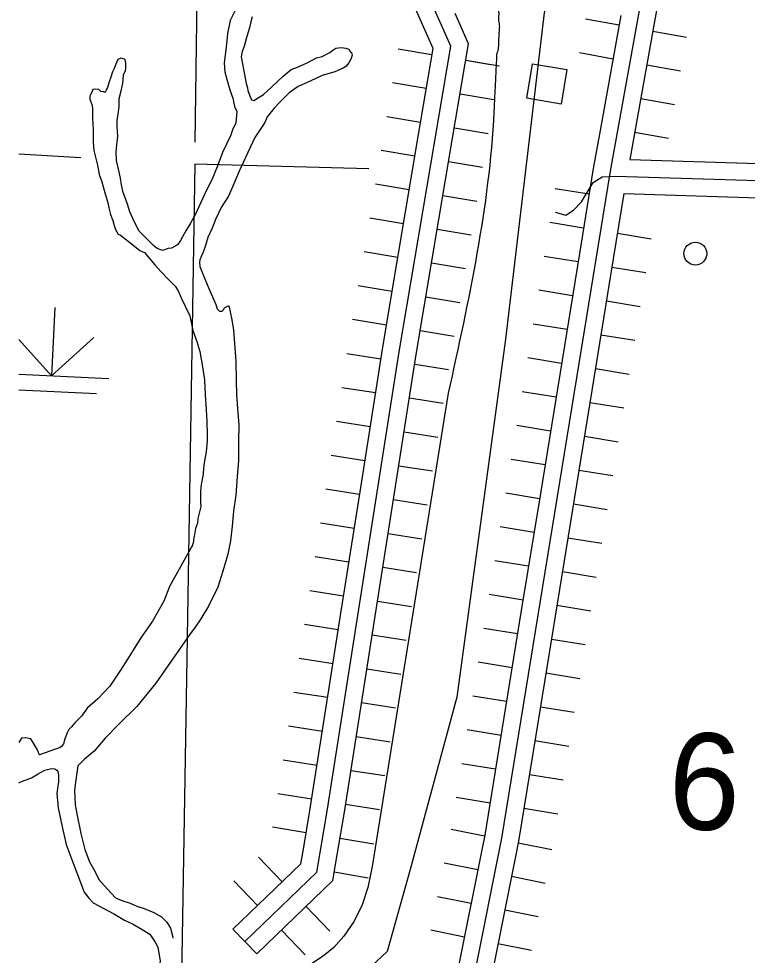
# Model space of a CAD drawing. Extents: x -4306 to 3843, y 131 to 8341.
# Drawn here: x -2796 to -2286, y 4860 to 5516 of the extents above; entities that cross this region are included whole.
import ezdxf

# ---------------------------------------------------------------- set-up
doc = ezdxf.new("R2010")
doc.units = 0
for name, color, linetype in [('32', 7, 'Continuous'), ('4', 7, 'Continuous'), ('52', 7, 'Continuous'), ('54', 7, 'Continuous'), ('55', 7, 'Continuous'), ('56', 7, 'Continuous'), ('57', 7, 'Continuous'), ('58', 7, 'Continuous'), ('59', 7, 'Continuous'), ('63', 7, 'Continuous')]:
    doc.layers.add(name, color=color, linetype=linetype)

msp = doc.modelspace()

# ---------------------------------------------------------------- linework, layer by layer
at = {"layer": '32'}
for p, q in [((-2512.37, 5510.35), (-2531.57, 5553.96)), ((-2493.45, 5497.18), (-2519.23, 5555.73)), ((-2493.45, 5497.18), (-2519.23, 5555.73)), ((-2358.5, 5538.6), (-2381.79, 5409.56)), ((-2358.5, 5538.6), (-2381.79, 5409.56)), ((-2347.42, 5532.45), (-2350.68, 5514.38)), ((-2481.02, 5498.73), (-2490.4, 5520.03)), ((-2374.3, 5518.64), (-2389.31, 5435.49)), ((-2350.68, 5514.38), (-2368.11, 5417.77)), ((-2505.89, 5495.63), (-2512.37, 5510.35)), ((-2492.38, 5431.28), (-2481.02, 5498.73)), ((-2529.5, 5283.08), (-2493.45, 5497.18)), ((-2529.5, 5283.08), (-2493.45, 5497.18)), ((-2516.05, 5435.26), (-2505.89, 5495.63)), ((-2530.07, 5351.94), (-2516.05, 5435.26)), ((-2389.31, 5435.49), (-2393.62, 5411.59)), ((-2506.41, 5347.96), (-2492.38, 5431.28)), ((-2368.11, 5417.77), (-2263.52, 5414.58)), ((-2381.79, 5409.56), (-2457.83, 4942.38)), ((-2381.79, 5409.56), (-2457.83, 4942.38)), ((-2393.62, 5411.59), (-2403.32, 5351.97)), ((-2387.37, 5405.54), (-2378.09, 5406.07)), ((-2378.09, 5406.07), (-1931.46, 5392.44)), ((-2401.96, 5388.06), (-2393.81, 5401.77)), ((-2393.81, 5401.77), (-2387.37, 5405.54)), ((-2372.18, 5393.88), (-2379.63, 5348.11)), ((-2372.18, 5393.88), (-2264.25, 5390.59)), ((-2407.46, 5382.35), (-2401.96, 5388.06)), ((-2420.27, 5380.9), (-2412.94, 5378.89)), ((-2412.94, 5378.89), (-2407.46, 5382.35)), ((-2541.34, 5285.01), (-2530.07, 5351.94)), ((-2517.65, 5281.15), (-2506.41, 5347.96)), ((-2403.32, 5351.97), (-2416.9, 5268.58)), ((-2379.63, 5348.11), (-2393.21, 5264.72)), ((-2580.01, 4961.24), (-2529.5, 5283.08)), ((-2580.01, 4961.24), (-2529.5, 5283.08)), ((-2543.94, 5268.47), (-2541.34, 5285.01)), ((-2520.23, 5264.75), (-2517.65, 5281.15)), ((-2557.04, 5185), (-2543.94, 5268.47)), ((-2416.9, 5268.58), (-2430.47, 5185.19)), ((-2533.33, 5181.28), (-2520.23, 5264.75)), ((-2393.21, 5264.72), (-2406.78, 5181.33)), ((-2570.14, 5101.53), (-2557.04, 5185)), ((-2430.47, 5185.19), (-2444.04, 5101.79)), ((-2546.43, 5097.81), (-2533.33, 5181.28)), ((-2406.78, 5181.33), (-2420.35, 5097.94)), ((-2583.24, 5018.07), (-2570.14, 5101.53)), ((-2559.53, 5014.34), (-2546.43, 5097.81)), ((-2444.04, 5101.79), (-2457.62, 5018.4)), ((-2420.35, 5097.94), (-2433.93, 5014.55)), ((-2591.86, 4963.17), (-2583.24, 5018.07)), ((-2568.17, 4959.31), (-2559.53, 5014.34)), ((-2457.62, 5018.4), (-2469.64, 4944.52)), ((-2433.93, 5014.55), (-2446.02, 4940.23)), ((-2596.65, 4934.79), (-2591.86, 4963.17)), ((-2587.21, 4918.62), (-2580.01, 4961.24)), ((-2587.21, 4918.62), (-2580.01, 4961.24)), ((-2572.99, 4930.79), (-2568.17, 4959.31)), ((-2457.83, 4942.38), (-2508.7, 4689.04)), ((-2457.83, 4942.38), (-2508.7, 4689.04)), ((-2469.64, 4944.52), (-2471.45, 4935.51)), ((-2446.02, 4940.23), (-2447.92, 4930.78)), ((-2598.39, 4924.51), (-2596.65, 4934.79)), ((-2471.45, 4935.51), (-2488.08, 4852.67)), ((-2576.04, 4912.73), (-2572.99, 4930.79)), ((-2447.92, 4930.78), (-2464.55, 4847.95)), ((-2646.01, 4878.57), (-2598.39, 4924.51)), ((-2637.67, 4869.93), (-2587.21, 4918.62)), ((-2637.67, 4869.93), (-2587.21, 4918.62)), ((-2629.34, 4861.3), (-2576.04, 4912.73)), ((-2629.34, 4861.3), (-2646.01, 4878.57))]:
    msp.add_line(p, q, dxfattribs=at)
at = {"layer": '4'}
for p, q in [((-2672.44, 5429.89), (-2664.73, 6032.85)), ((-2796.1, 5421.68), (-2752.56, 5419.12))]:
    msp.add_line(p, q, dxfattribs=at)
at = {"layer": '54'}
for p, q in [((-2672.64, 5414.44), (-2678.68, 5054.24)), ((-2550.85, 5411.35), (-2672.64, 5414.44)), ((-2678.68, 5054.24), (-2685.12, 4670.32))]:
    msp.add_line(p, q, dxfattribs=at)
at = {"layer": '55'}
for p, q in [((-2674.6, 5147.11), (-2690.59, 5118.73)), ((-2690.59, 5118.73), (-2694.54, 5108.5)), ((-2694.54, 5108.5), (-2702.37, 5094.47)), ((-2702.37, 5094.47), (-2710.5, 5082.69)), ((-2710.5, 5082.69), (-2718.32, 5070.26)), ((-2718.32, 5070.26), (-2724.83, 5060.07)), ((-2724.83, 5060.07), (-2732.31, 5048.92)), ((-2732.31, 5048.92), (-2740.72, 5040.04)), ((-2740.72, 5040.04), (-2747.83, 5033.71)), ((-2747.83, 5033.71), (-2752.05, 5027.98)), ((-2752.05, 5027.98), (-2756.9, 5023.22)), ((-2759.18, 5020.36), (-2761.12, 5018.46)), ((-2756.9, 5023.22), (-2759.18, 5020.36)), ((-2794.12, 5012.45), (-2795.42, 5010.54)), ((-2791.24, 5012.73), (-2794.12, 5012.45)), ((-2787.73, 5012.05), (-2791.24, 5012.73)), ((-2786.47, 5010.11), (-2787.73, 5012.05)), ((-2763.75, 5012.07), (-2764.74, 5008.55)), ((-2762.1, 5016.22), (-2763.75, 5012.07)), ((-2761.12, 5018.46), (-2762.1, 5016.22)), ((-2795.42, 5010.54), (-2796.1, 5009.32)), ((-2783.02, 5004.28), (-2786.47, 5010.11)), ((-2767.01, 5006.01), (-2781.46, 5000.73)), ((-2766.05, 5006.64), (-2767.01, 5006.01)), ((-2764.74, 5008.55), (-2766.05, 5006.64)), ((-2781.78, 5001.06), (-2783.02, 5004.28)), ((-2781.46, 5000.73), (-2781.78, 5001.06))]:
    msp.add_line(p, q, dxfattribs=at)
for points in [[(-2632.68, 5517.79), (-2633.69, 5513.31), (-2634.37, 5510.11), (-2635.69, 5506.27), (-2636.69, 5502.43), (-2638.02, 5497.95), (-2638.69, 5495.71), (-2639.67, 5493.47), (-2640.36, 5489.63), (-2637.94, 5477.4), (-2636.73, 5470.96), (-2635.8, 5468.06), (-2635.5, 5466.13), (-2634.57, 5463.55), (-2633.02, 5459.67), (-2631.43, 5459.01), (-2629.49, 5460.27), (-2626.59, 5462.16), (-2624.66, 5463.42), (-2621.75, 5465.96), (-2614.97, 5472.29), (-2610.77, 5476.09), (-2605.28, 5480.84), (-2600.78, 5482.39), (-2594.03, 5485.52), (-2587.59, 5488.97), (-2583.43, 5489.88), (-2578.28, 5492.71), (-2576.02, 5494.28), (-2574.08, 5495.86), (-2570.24, 5496.14), (-2567.05, 5495.78), (-2564.82, 5495.11), (-2563.88, 5493.49), (-2562.93, 5492.83), (-2562.63, 5490.9), (-2563.29, 5488.66), (-2563.62, 5487.71), (-2564.93, 5485.47), (-2566.87, 5482.93), (-2568.81, 5481.67), (-2574.59, 5479.17), (-2583.57, 5476.72), (-2591.94, 5472.65), (-2600.29, 5468.9), (-2606.74, 5464.48), (-2613.53, 5457.82), (-2617.09, 5453.69), (-2621.96, 5447.65), (-2623.6, 5443.82), (-2630.76, 5433.31), (-2637.31, 5419.27), (-2641.58, 5409.69), (-2645.51, 5400.75), (-2649.13, 5392.12), (-2654.34, 5384.16), (-2658.27, 5375.86), (-2660.58, 5369.79), (-2663.53, 5363.08), (-2665.19, 5357.64), (-2666.84, 5352.84), (-2668.15, 5350.29), (-2669.14, 5347.41), (-2669.48, 5345.81), (-2669.19, 5342.92), (-2667.95, 5339.37), (-2665.77, 5334.21), (-2662.97, 5327.43), (-2660.48, 5321.62), (-2657.98, 5316.13), (-2657.05, 5313.22), (-2655.47, 5311.6), (-2654.51, 5311.59), (-2653.55, 5311.58), (-2652.91, 5312.21), (-2651.93, 5313.8), (-2649.35, 5315.38), (-2649.03, 5315.37), (-2648.73, 5314.4), (-2646.91, 5305.39), (-2645.71, 5298.31), (-2644.04, 5276.45), (-2643.87, 5262.64), (-2643.66, 5253.33)], [(-2644.47, 5522.11), (-2648.07, 5515.09), (-2649.77, 5506.12), (-2650.83, 5496.5), (-2652.23, 5485.6), (-2651.67, 5479.17), (-2650.14, 5473.05), (-2648.29, 5466.61), (-2646.12, 5460.8), (-2644.9, 5455.01), (-2643.34, 5451.45), (-2643.73, 5446), (-2644.07, 5443.44), (-2646.37, 5438.65), (-2647.69, 5434.49), (-2653.26, 5422.68), (-2657.21, 5412.77), (-2660.83, 5403.51)], [(-2660.83, 5403.51), (-2664.76, 5395.85), (-2668.69, 5387.23), (-2672.3, 5379.57), (-2675.89, 5373.19), (-2679.15, 5367.77), (-2681.43, 5363.62), (-2682.74, 5361.07), (-2684.69, 5358.21), (-2685.98, 5357.26), (-2689.2, 5355.69), (-2691.44, 5355.4), (-2695.29, 5354.16), (-2699.11, 5355.5), (-2701.65, 5357.46), (-2704.18, 5360.06), (-2707.97, 5363.96), (-2711.77, 5367.54), (-2713.65, 5371.09), (-2716.15, 5376.58), (-2718.33, 5381.11), (-2719.87, 5386.58), (-2721.73, 5391.75), (-2722.98, 5394.65), (-2724.2, 5400.13), (-2724.79, 5404.63), (-2726, 5410.1), (-2727.52, 5417.19), (-2727.78, 5422.97), (-2727.4, 5428.1), (-2726.69, 5434.19), (-2727.26, 5440.62), (-2727.21, 5445.12), (-2726.52, 5449.61), (-2725.82, 5454.74), (-2725.76, 5460.51), (-2724.41, 5465.96), (-2723.08, 5471.08), (-2722.69, 5477.17), (-2721.38, 5480.05), (-2721.04, 5481.33), (-2721.01, 5484.54), (-2721, 5485.18), (-2721.31, 5486.15), (-2721.61, 5487.76), (-2721.93, 5488.08), (-2724.48, 5488.76), (-2726.73, 5487.82), (-2728.04, 5484.63), (-2729.36, 5481.43), (-2730.34, 5479.2), (-2731.66, 5475.36), (-2732.66, 5472.16), (-2733.98, 5468.32), (-2734.64, 5467.05), (-2735.3, 5465.13), (-2735.94, 5464.82), (-2736.58, 5465.15), (-2738.49, 5465.49), (-2740.08, 5466.8), (-2742.31, 5467.14), (-2744.23, 5466.85), (-2744.57, 5465.57), (-2745.88, 5463.01), (-2746.21, 5462.06), (-2746.23, 5460.13), (-2744.99, 5456.26), (-2744.38, 5453.68), (-2744.42, 5450.15), (-2744.46, 5446.94), (-2744.18, 5442.76), (-2743.91, 5438.58), (-2743.96, 5434.09), (-2744.01, 5429.92), (-2743.43, 5424.13), (-2742.52, 5420.26), (-2740.99, 5413.82), (-2739.79, 5407.38), (-2737.92, 5402.22), (-2735.46, 5393.84), (-2733.92, 5388.37), (-2733.01, 5383.86), (-2731.79, 5379.35), (-2730.23, 5375.15), (-2729.31, 5371.61), (-2728.39, 5368.71), (-2726.51, 5365.47), (-2724.91, 5364.81), (-2715.09, 5356.98), (-2711.28, 5354.04), (-2708.1, 5352.72), (-2700.84, 5343.96), (-2696.42, 5339.09), (-2691.68, 5334.21), (-2686.62, 5329.01), (-2684.42, 5325.77), (-2682.23, 5320.93), (-2679.42, 5315.11), (-2676.3, 5308.33), (-2674.18, 5298.03), (-2671.38, 5290.28)], [(-2671.38, 5290.28), (-2669.23, 5283.19), (-2667.43, 5272.57), (-2665.93, 5263.56), (-2665.41, 5252.96), (-2664.88, 5242.68), (-2664.34, 5234), (-2664.12, 5225.33), (-2664.17, 5220.83), (-2664.9, 5213.13), (-2665.93, 5206.73), (-2666.62, 5201.92), (-2666.99, 5197.43), (-2668.36, 5190.06), (-2668.73, 5185.57), (-2668.81, 5177.86), (-2668.53, 5174.65), (-2670.54, 5166.32), (-2670.9, 5163.12), (-2672.22, 5159.28), (-2672.91, 5155.11), (-2673.59, 5151.59), (-2673.6, 5149.98), (-2674.6, 5147.11), (-2674.93, 5146.15)], [(-2643.66, 5253.33), (-2642.81, 5243.04), (-2641.98, 5232.11), (-2642.11, 5220.23), (-2642.26, 5207.07), (-2643.03, 5195.52), (-2644.13, 5182.69), (-2645.54, 5171.47), (-2646.62, 5160.88), (-2647.69, 5150.62), (-2649.72, 5141.34), (-2653.05, 5129.5), (-2656.69, 5118.3), (-2663.24, 5104.9), (-2668.46, 5095.97), (-2673, 5089.61), (-2675.93, 5085.47)], [(-2675.93, 5085.47), (-2699.98, 5051.09), (-2713.28, 5034.56), (-2725.89, 5022.19), (-2735.6, 5012.36), (-2743.37, 5003.46), (-2750.16, 4997.45), (-2754.69, 4993.01), (-2756.07, 4983.39), (-2757.12, 4976.02), (-2756.59, 4965.74), (-2755.08, 4958.33), (-2752.66, 4945.78), (-2749.91, 4934.51), (-2746.49, 4925.79), (-2742.72, 4919.32), (-2739.91, 4913.51), (-2733.91, 4906.69), (-2728.22, 4900.52), (-2723.13, 4898.53), (-2718.03, 4896.86), (-2713.26, 4894.87), (-2708.16, 4893.2), (-2701.47, 4890.23), (-2696.07, 4887.27), (-2692.27, 4883.69), (-2689.76, 4879.48), (-2688.24, 4873.04), (-2688.12, 4872.44)], [(-2796.1, 4981.14), (-2793.5, 4982.26), (-2787.08, 4984.75), (-2782.57, 4987.58), (-2777.75, 4990.09), (-2773.25, 4991.32), (-2770.7, 4990.96), (-2769.43, 4989.98), (-2768.8, 4989.01), (-2768.49, 4988.69), (-2768.2, 4986.11), (-2768.24, 4981.94), (-2768.94, 4977.13), (-2769.3, 4973.6), (-2768.45, 4963.64), (-2765.72, 4950.44), (-2762.98, 4937.88), (-2758.01, 4924.97), (-2754.9, 4916.91), (-2750.24, 4904.65), (-2747.09, 4900.43), (-2743.93, 4897.18), (-2728.99, 4889.29), (-2722, 4885.03), (-2715.96, 4882.06), (-2709.6, 4878.45), (-2704.2, 4875.17)], [(-2704.2, 4875.17), (-2700.43, 4869.66), (-2698.55, 4866.11), (-2697.06, 4856.46), (-2698.11, 4847.8), (-2699.47, 4841.07), (-2700.85, 4832.42), (-2701.9, 4823.76), (-2703.57, 4818), (-2705.88, 4810.97), (-2707.21, 4806.49), (-2713.06, 4798.21), (-2723.09, 4788.38), (-2731.13, 4784.63), (-2738.53, 4780.23), (-2748.54, 4772), (-2764.07, 4756.46), (-2769.87, 4752.04), (-2777.32, 4744.11), (-2785.42, 4734.57), (-2794.51, 4722.81), (-2796.1, 4720.2)]]:
    msp.add_lwpolyline(points, dxfattribs=at)
at = {"layer": '56'}
for points in [[(-2419.98, 5561.32), (-2428.14, 5520.43), (-2455.18, 5291.97), (-2489.16, 5041.29), (-2521.81, 4920.48), (-2538.06, 4862.99), (-2570.96, 4832.09), (-2659.53, 4768.87)], [(-2495.25, 5254.04), (-2548.56, 4922.67), (-2551.6, 4907.94), (-2555.58, 4895.79), (-2561.14, 4884.3), (-2568.3, 4873.79), (-2575.42, 4865.85), (-2581.56, 4860.79), (-2587.04, 4857), (-2707.87, 4776.95)]]:
    msp.add_lwpolyline(points, dxfattribs=at)
msp.add_spline([(-2451.35, 5677.81), (-2451.55, 5673.65), (-2452.59, 5669.52), (-2452.79, 5665.35), (-2453.83, 5661.22), (-2454.03, 5657.06), (-2455.07, 5652.93), (-2455.28, 5648.76), (-2455.48, 5644.59), (-2455.68, 5640.42), (-2456.72, 5636.3), (-2457.76, 5632.17), (-2457.96, 5628), (-2458.17, 5623.83), (-2459.2, 5619.71), (-2460.24, 5615.58), (-2461.28, 5611.45), (-2461.48, 5607.29), (-2462.52, 5603.16), (-2462.72, 5598.99), (-2463.76, 5594.86), (-2463.96, 5590.7), (-2465, 5586.57), (-2465.2, 5582.4), (-2466.24, 5578.27), (-2466.44, 5574.11), (-2466.65, 5569.94), (-2466.85, 5565.77), (-2467.06, 5561.6), (-2467.26, 5557.43), (-2466.63, 5553.23), (-2466, 5549.02), (-2465.37, 5544.81), (-2463.91, 5540.56), (-2461.57, 5537.1), (-2460.94, 5532.89), (-2460.31, 5528.69), (-2460.52, 5524.52), (-2459.89, 5520.31), (-2460.09, 5516.14), (-2459.46, 5511.93), (-2459.66, 5507.76), (-2459.87, 5503.6), (-2460.07, 5499.43), (-2460.28, 5495.26), (-2461.31, 5491.13), (-2461.52, 5486.97), (-2461.72, 5482.8), (-2461.92, 5478.63), (-2462.13, 5474.46), (-2462.33, 5470.29), (-2462.45, 5467.79), (-2462.66, 5463.63), (-2462.86, 5459.46), (-2463.07, 5455.29), (-2463.27, 5451.12), (-2495.25, 5254.04)], degree=3, dxfattribs=at)
at = {"layer": '57'}
msp.add_circle((-2322.1, 5351.89), 8, dxfattribs=at)
at = {"layer": '58'}
msp.add_lwpolyline([(-2416.12, 5456.64), (-2440.27, 5460.68), (-2436.23, 5484.83), (-2412.08, 5480.79)], close=True, dxfattribs=at)
at = {"layer": '59'}
for p, q in [((-2770.7, 5314.23), (-2773.04, 5266.29)), ((-2773.04, 5266.29), (-2796.1, 5291.72)), ((-2773.04, 5266.29), (-2743.41, 5293.16)), ((-2796.1, 5267.41), (-2733.08, 5264.33)), ((-2796.1, 5256.49), (-2741.61, 5253.83))]:
    msp.add_line(p, q, dxfattribs=at)
at = {"layer": '63'}
for p, q in [((-2399.11, 5516.29), (-2375.49, 5512.03)), ((-2399.11, 5516.29), (-2375.49, 5512.03)), ((-2351.87, 5507.76), (-2328.25, 5503.5)), ((-2351.87, 5507.76), (-2328.25, 5503.5)), ((-2506.65, 5491.12), (-2530.31, 5495.11)), ((-2506.65, 5491.12), (-2530.31, 5495.11)), ((-2403.38, 5492.67), (-2379.76, 5488.4)), ((-2459.31, 5483.15), (-2482.98, 5487.14)), ((-2465.62, 5484.22), (-2482.98, 5487.14)), ((-2356.14, 5484.14), (-2332.51, 5479.88)), ((-2510.63, 5467.45), (-2534.3, 5471.44)), ((-2463.29, 5459.48), (-2486.96, 5463.47)), ((-2360.4, 5460.52), (-2336.78, 5456.26)), ((-2514.61, 5443.78), (-2538.28, 5447.77)), ((-2467.28, 5435.81), (-2490.94, 5439.8)), ((-2364.66, 5436.9), (-2341.04, 5432.64)), ((-2364.66, 5436.9), (-2341.04, 5432.64)), ((-2518.6, 5420.11), (-2542.27, 5424.1)), ((-2518.6, 5420.11), (-2542.27, 5424.1)), ((-2471.26, 5412.14), (-2494.93, 5416.13)), ((-2471.26, 5412.14), (-2494.93, 5416.13)), ((-2522.58, 5396.44), (-2546.25, 5400.43)), ((-2475.24, 5388.47), (-2498.91, 5392.46)), ((-2420.23, 5397.52), (-2396.54, 5393.66)), ((-2526.57, 5372.77), (-2550.24, 5376.76)), ((-2424.08, 5373.83), (-2400.39, 5369.97)), ((-2424.08, 5373.83), (-2400.39, 5369.97)), ((-2479.23, 5364.8), (-2502.9, 5368.79)), ((-2376.7, 5366.12), (-2353.01, 5362.26)), ((-2376.7, 5366.12), (-2353.01, 5362.26)), ((-2530.55, 5349.1), (-2554.22, 5353.09)), ((-2530.55, 5349.1), (-2554.22, 5353.09)), ((-2427.94, 5350.14), (-2404.25, 5346.28)), ((-2483.21, 5341.14), (-2506.88, 5345.12)), ((-2483.21, 5341.14), (-2506.88, 5345.12)), ((-2380.56, 5342.43), (-2356.87, 5338.57)), ((-2534.54, 5325.43), (-2558.21, 5329.42)), ((-2487.2, 5317.47), (-2510.87, 5321.45)), ((-2431.8, 5326.45), (-2408.1, 5322.59)), ((-2384.41, 5318.74), (-2360.72, 5314.88)), ((-2538.52, 5301.77), (-2562.19, 5305.75)), ((-2435.65, 5302.76), (-2411.96, 5298.9)), ((-2435.65, 5302.76), (-2411.96, 5298.9)), ((-2491.18, 5293.8), (-2514.85, 5297.78)), ((-2388.27, 5295.05), (-2364.58, 5291.19)), ((-2388.27, 5295.05), (-2364.58, 5291.19)), ((-2542.45, 5277.95), (-2566.16, 5281.67)), ((-2542.45, 5277.95), (-2566.16, 5281.67)), ((-2439.51, 5279.07), (-2415.82, 5275.21)), ((-2495.03, 5270.51), (-2518.74, 5274.23)), ((-2495.03, 5270.51), (-2518.74, 5274.23)), ((-2392.13, 5271.35), (-2368.43, 5267.5)), ((-2546.17, 5254.24), (-2569.88, 5257.96)), ((-2443.36, 5255.38), (-2419.67, 5251.52)), ((-2498.75, 5246.8), (-2522.46, 5250.52)), ((-2395.98, 5247.66), (-2372.29, 5243.81)), ((-2549.89, 5230.53), (-2573.61, 5234.25)), ((-2447.22, 5231.68), (-2423.53, 5227.83)), ((-2447.22, 5231.68), (-2423.53, 5227.83)), ((-2502.47, 5223.08), (-2526.18, 5226.81)), ((-2399.84, 5223.97), (-2376.15, 5220.12)), ((-2399.84, 5223.97), (-2376.15, 5220.12)), ((-2553.62, 5206.82), (-2577.33, 5210.54)), ((-2553.62, 5206.82), (-2577.33, 5210.54)), ((-2506.19, 5199.37), (-2529.9, 5203.09)), ((-2506.19, 5199.37), (-2529.9, 5203.09)), ((-2451.08, 5207.99), (-2427.38, 5204.14)), ((-2403.69, 5200.28), (-2380, 5196.43)), ((-2557.34, 5183.1), (-2581.05, 5186.82)), ((-2454.93, 5184.3), (-2431.24, 5180.45)), ((-2509.91, 5175.66), (-2533.63, 5179.38)), ((-2407.55, 5176.59), (-2383.86, 5172.74)), ((-2561.06, 5159.39), (-2584.77, 5163.11)), ((-2458.79, 5160.61), (-2435.1, 5156.76)), ((-2458.79, 5160.61), (-2435.1, 5156.76)), ((-2513.64, 5151.95), (-2537.35, 5155.67)), ((-2411.41, 5152.9), (-2387.72, 5149.04)), ((-2411.41, 5152.9), (-2387.72, 5149.04)), ((-2564.78, 5135.68), (-2588.49, 5139.4)), ((-2564.78, 5135.68), (-2588.49, 5139.4)), ((-2462.64, 5136.92), (-2438.95, 5133.07)), ((-2517.36, 5128.23), (-2541.07, 5131.96)), ((-2517.36, 5128.23), (-2541.07, 5131.96)), ((-2415.26, 5129.21), (-2391.57, 5125.35)), ((-2568.5, 5111.97), (-2592.22, 5115.69)), ((-2466.5, 5113.23), (-2442.81, 5109.38)), ((-2521.08, 5104.52), (-2544.79, 5108.24)), ((-2419.12, 5105.52), (-2395.43, 5101.66)), ((-2572.23, 5088.25), (-2595.94, 5091.98)), ((-2524.8, 5080.81), (-2548.51, 5084.53)), ((-2470.36, 5089.54), (-2446.66, 5085.68)), ((-2470.36, 5089.54), (-2446.66, 5085.68)), ((-2422.97, 5081.83), (-2399.28, 5077.97)), ((-2422.97, 5081.83), (-2399.28, 5077.97)), ((-2575.95, 5064.54), (-2599.66, 5068.26)), ((-2575.95, 5064.54), (-2599.66, 5068.26)), ((-2474.21, 5065.85), (-2450.52, 5061.99)), ((-2528.52, 5057.1), (-2552.24, 5060.82)), ((-2528.52, 5057.1), (-2552.24, 5060.82)), ((-2426.83, 5058.14), (-2403.14, 5054.28)), ((-2579.67, 5040.83), (-2603.38, 5044.55)), ((-2478.07, 5042.16), (-2454.38, 5038.3)), ((-2532.25, 5033.39), (-2555.96, 5037.11)), ((-2430.69, 5034.45), (-2407, 5030.59)), ((-2583.39, 5017.12), (-2607.1, 5020.84)), ((-2535.97, 5009.67), (-2559.68, 5013.4)), ((-2481.92, 5018.47), (-2458.23, 5014.61)), ((-2481.92, 5018.47), (-2458.23, 5014.61)), ((-2434.54, 5010.76), (-2410.85, 5006.9)), ((-2434.54, 5010.76), (-2410.85, 5006.9)), ((-2587.11, 4993.41), (-2610.83, 4997.13)), ((-2587.11, 4993.41), (-2610.83, 4997.13)), ((-2485.78, 4994.78), (-2462.09, 4990.92)), ((-2539.69, 4985.96), (-2563.4, 4989.68)), ((-2539.69, 4985.96), (-2563.4, 4989.68)), ((-2438.4, 4987.06), (-2414.71, 4983.21)), ((-2590.84, 4969.69), (-2614.55, 4973.41)), ((-2489.64, 4971.09), (-2465.94, 4967.23)), ((-2543.41, 4962.25), (-2567.12, 4965.97)), ((-2442.25, 4963.37), (-2418.56, 4959.52)), ((-2594.73, 4946.15), (-2618.4, 4950.15)), ((-2493.28, 4948.7), (-2469.75, 4943.98)), ((-2493.28, 4948.7), (-2469.75, 4943.98)), ((-2547.4, 4938.16), (-2571.07, 4942.15)), ((-2446.22, 4939.25), (-2422.68, 4934.53)), ((-2446.22, 4939.25), (-2422.68, 4934.53)), ((-2611.46, 4911.9), (-2628.13, 4929.18)), ((-2498.01, 4925.17), (-2474.48, 4920.45)), ((-2551.4, 4914.49), (-2575.06, 4918.49)), ((-2551.4, 4914.49), (-2575.06, 4918.49)), ((-2450.94, 4915.72), (-2427.41, 4911)), ((-2628.73, 4895.24), (-2645.4, 4912.51)), ((-2502.73, 4901.64), (-2479.2, 4896.91)), ((-2578.13, 4877.36), (-2594.79, 4894.63)), ((-2455.67, 4892.19), (-2432.13, 4887.46)), ((-2595.4, 4860.69), (-2612.07, 4877.96)), ((-2507.46, 4878.11), (-2483.93, 4873.38)), ((-2507.46, 4878.11), (-2483.93, 4873.38)), ((-2460.39, 4868.66), (-2436.86, 4863.93)), ((-2460.39, 4868.66), (-2436.86, 4863.93))]:
    msp.add_line(p, q, dxfattribs=at)

# ---------------------------------------------------------------- texts
at = {"layer": '52'}
msp.add_text('6', height=67.59, rotation=357.20058, dxfattribs=at).set_placement((-2342.28, 4949.61))

doc.saveas('drawing.dxf')
